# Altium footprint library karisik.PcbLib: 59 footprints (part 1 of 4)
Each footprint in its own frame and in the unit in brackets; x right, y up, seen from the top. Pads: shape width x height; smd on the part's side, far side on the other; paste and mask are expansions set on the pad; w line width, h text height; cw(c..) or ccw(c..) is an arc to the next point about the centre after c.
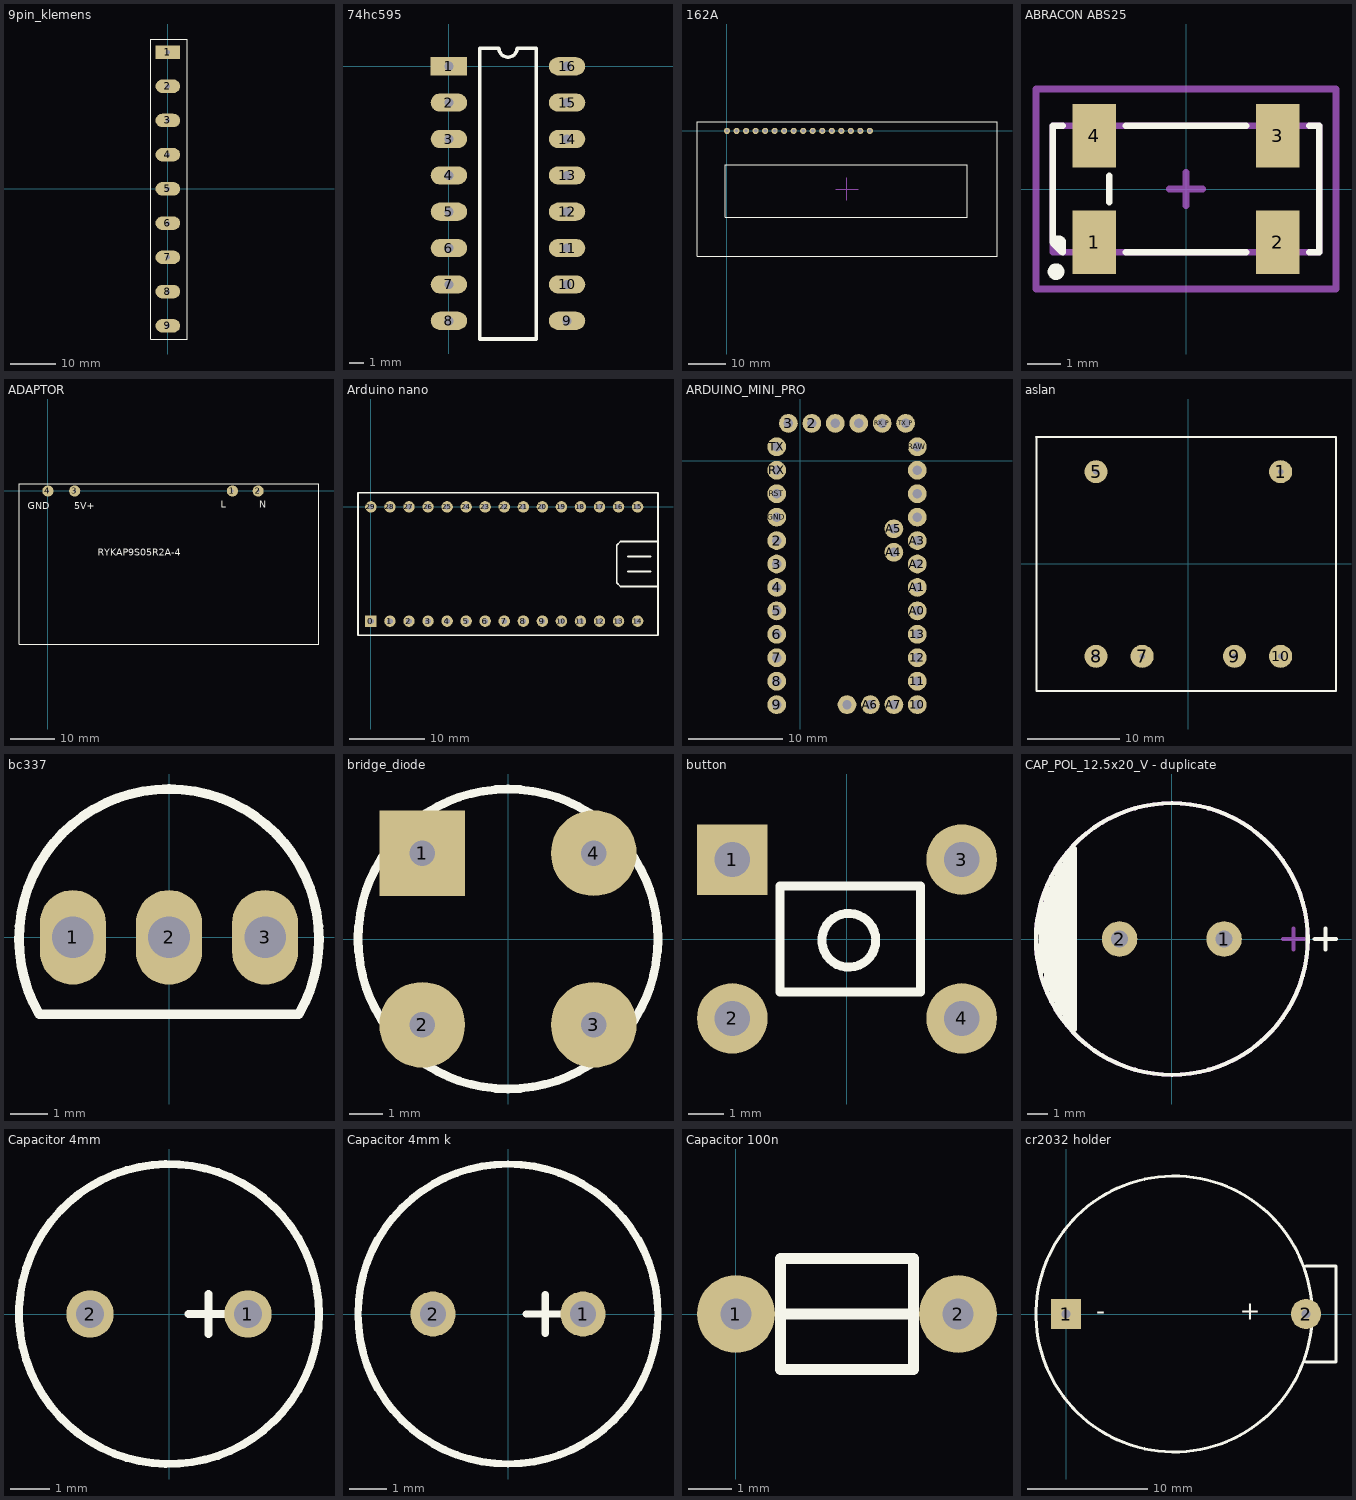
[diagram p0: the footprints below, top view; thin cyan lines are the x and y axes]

## 9pin_klemens [mm]
pads (9):
  rect 5.5x3 hole 1: 1(0,30.48)
  oval 5.5x3 hole 1: 2(0,22.86) 3(0,15.24) 4(0,7.62) 5(0,0) 6(0,-7.62) 7(0,-15.24) 8(0,-22.86) 9(0,-30.48)
Top Overlay:
  lines w0.254: -3.8,-33.42 4.3,-33.42 4.3,33.38 -3.8,33.38 -3.8,-33.42

## 74hc595 [mil]
pads (16):
  rect 100x50 hole 25: 1(0,0)
  oval 100x50 hole 25: 2(0,-100) 3(0,-200) 4(0,-300) 5(0,-400) 6(0,-500) 7(0,-600) 8(0,-700) 9(325,-700) 10(325,-600) 11(325,-500) 12(325,-400) 13(325,-300) 14(325,-200) 15(325,-100) 16(325,0)
Top Overlay:
  lines w10: 85,-750 240,-750 240,50 187.5,50 cw(c162.5,50) 137.5,50 85,50 85,-750

## 162A [mil]
pads (16):
  round 65 hole 35.43: 1(0,0) 2(100,0) 3(200,0) 4(300,0) 5(400,0) 6(500,0) 7(600,0) 8(700,0) 9(800,0) 10(900,0) 11(1000,0) 12(1100,0) 13(1200,0) 14(1300,0) 15(1400,0) 16(1500,0)
Top Overlay:
  lines w7.87: -314.96,-1318.9 2834.65,-1318.9 2834.65,98.43 -314.96,98.43 -314.96,-1318.9 ; -19.68,-905.51 2519.69,-905.51 2519.69,-354.33 -19.68,-354.33 -19.68,-905.51
Mechanical 15:
  lines w10: 1141.73,-610.24 1377.95,-610.24 ; 1259.84,-728.35 1259.84,-492.13

## ABRACON ABS25 [mm]
height 2.5
pads (4):
  rect 1.3x1.9 smd: 1(-2.75,-1.6) 2(2.75,-1.6) 3(2.75,1.6) 4(-2.75,1.6)
Top Overlay:
  circle w0.25: c-3.9,-2.48 r0.125
  region: -4,-1.5 -4,-1.6 -3.7,-1.9 -3.7,-1.6 -3.8,-1.5
  lines w0.2: -3.7,1.9 -4,1.9 -4,0 -4,-1.6 ; -2.3,-0.4 -2.3,0.4 ; -1.8,-1.9 1.8,-1.9 ; -1.8,1.9 1.8,1.9 ; 3.7,-1.9 4,-1.9 4,0 4,1.9 3.7,1.9 ; -4,-1.6 cw(c-3.9,-1.6) -3.9,-1.5 -3.8,-1.5 cw(c-3.8,-1.6) -3.7,-1.6 -3.7,-1.9 -4,-1.6
Mechanical 1:
  lines w0.2: -4,-1.9 -4,1.9 4,1.9 4,-1.9 -4,-1.9
Mechanical 15:
  lines w0.2: -0.5,0 0.5,0 ; 0,-0.5 0,0.5 ; -4.5,-3 -4.5,3 4.5,3 4.5,-3 -4.5,-3
3D body: height 2.5, standoff 0, extent -4,-1.9 4,1.9

## ADAPTOR [mm]
pads (4):
  round 2.5 hole 0.6: 1(41.453,0) 2(47.244,0) 3(6.02,0) 4(0,0)
Top Overlay:
  lines w0.254: -1.993,1.609 -6.493,1.609 ; 0,1.6 -6.485,1.6 ; 41.453,1.6 -6.485,1.6 ; -6.493,1.609 60.909,1.609 60.909,-34.417 -6.493,-34.417 -6.493,1.609 ; -6.493,1.609 -6.485,1.6
  text "RYKAP9S05R2A-4" at 11.227,-14.554 h1.52
  text "GND" at -4.521,-4.089 h1.52
  text "5V+" at 5.944,-4.089 h1.52
  text "L" at 38.811,-3.785 h1.52
  text "N" at 47.498,-3.785 h1.52

## Arduino nano [mil] "arduino nano"
height 1700
pads (30):
  rect 60x60 hole 30: 0(0,-600)
  round 60 hole 30: 1(100,-600) 2(200,-600) 3(300,-600) 4(400,-600) 5(500,-600) 6(600,-600) 7(700,-600) 8(800,-600) 9(900,-600) 10(1000,-600) 11(1100,-600) 12(1200,-600) 13(1300,-600) 14(1400,-600) 15(1400,0) 16(1300,0) 17(1200,0) 18(1100,0) 19(1000,0) 20(900,0) 21(800,0) 22(700,0) 23(600,0) 24(500,0) 25(400,0) 26(300,0) 27(200,0) 28(100,0) 29(0,0)
Top Overlay:
  lines w10: 1349.61,-339.37 1467.72,-339.37 ; 1349.61,-260.63 1467.72,-260.63 ; 1507.09,-418.11 1329.92,-418.11 1310.24,-418.11 1290.55,-398.43 1290.55,-359.06 1290.55,-201.57 1310.24,-181.89 1507.09,-181.89 ; -67.72,-674.02 -67.72,14.96 -67.72,74.02 1507.09,74.02 1507.09,34.65 1507.09,-674.02 -67.72,-674.02

## ARDUINO_MINI_PRO [mm]
pads (35):
  round 2 hole 1: 2(-2.5,-8.5) 2(1.25,4) 3(-2.5,-11) 3(-1.25,4) 4(-2.5,-13.5) 5(-2.5,-16) 6(-2.5,-18.5) 7(-2.5,-21) 8(-2.5,-23.5) 9(-2.5,-26) 10(12.5,-26) 11(12.5,-23.5) 12(12.5,-21) 13(12.5,-18.5) A0(12.5,-16) A1(12.5,-13.5) A2(12.5,-11) A3(12.5,-8.5) A4(10,-9.75) A5(10,-7.25) A6(7.5,-26) A7(10,-26) GND(-2.5,-6) GND_2(12.5,-1) GND_P(3.75,4) GND_SPI(5,-26) RAW(12.5,1.5) RST(-2.5,-3.5) RST_2(12.5,-3.5) RST_P(6.25,4) RX(-2.5,-1) RX_P(8.75,4) TX(-2.5,1.5) TX_P(11.25,4) VCC_2(12.5,-6)

## aslan [mm]
pads (6):
  round 2.5 hole 0.6: 1(10,10) 5(-10,10) 7(-5,-10) 8(-10,-10) 9(5,-10) 10(10,-10)
Top Overlay:
  lines w0.254: -16.5,13.75 16,13.75 16,-13.75 -16.4,-13.75 -16.45,-13.7 -16.45,13.75 -11.95,13.75

## bc337 [mm]
height 10
pads (3):
  oval 1.75x2.5 hole 1.1: 1(-2.54,0) 2(0,0) 3(2.54,0)
Top Overlay:
  lines w0.254: -3.429,-2.032 cw(c0,-0.043) 3.429,-2.032 -3.429,-2.032
Mechanical 15:
  lines w0.2: -0.5,0 0.5,0 ; 0,-0.5 0,0.5

## bridge_diode [mil]
height 217
pads (4):
  rect 100x100 hole 30: 1(-100,100)
  round 100 hole 30: 2(-100,-100) 3(100,-100) 4(100,100)
Top Overlay:
  circle w10: c0,0 r174.83

## button [mm]
pads (4):
  rect 2x2 hole 1: 1(-3.25,2.25)
  round 2 hole 1: 2(-3.25,-2.25) 3(3.25,2.25) 4(3.25,-2.25)
Top Overlay:
  circle w0.254: c0.052,-0.036 r0.762
  lines w0.254: -1.9,-1.5 2.076,-1.5 2.076,-1.179 2.076,1.107 2.076,1.5 -1.9,1.5 -1.9,-1.5

## CAP_POL_12.5x20_V - duplicate [mm]
pads (2):
  round 1.7 hole 0.8: 1(2.5,0) 2(-2.5,0)
Top Overlay:
  circle w0.2: c0,0 r6.5
  lines w0.2: 6.838,0 7.854,0 ; 7.346,-0.508 7.346,0.508
  lines w0.3: -6.223,-1.524 -6.223,1.651 ; -5.969,-2.413 -5.969,2.413 ; -5.715,-2.921 -5.715,2.921 ; -5.461,-3.302 -5.461,3.175 ; -5.334,-3.556 -5.334,3.556 ; -5.08,-3.81 -5.08,3.81 ; -4.953,-2.286 -4.953,4.064 ; -4.699,-4.318 -4.699,4.318 ; -4.953,4.064 -4.953,-4.064 -4.953,4.064
Mechanical 13:
  circle w0.2: c0,0 r6.5
  lines w0.2: 5.314,0 6.33,0 ; 5.822,-0.508 5.822,0.508
  text ".Designator" at -2.159,-3.175 h2.5
3D body: height 20.01, standoff -2.7, extent -6.206,-6.25 6.25,6.25

## Capacitor 4mm [mm]
pads (2):
  round 1.2 hole 0.7: 1(2,0) 2(-2,0)
Top Overlay:
  circle w0.2: c0,0 r3.8
  lines w0.2: 0.492,0 1.508,0 ; 1,-0.508 1,0.508

## Capacitor 4mm k [mm]
pads (2):
  round 1.2 hole 0.7: 1(2,0) 2(-2,0)
Top Overlay:
  circle w0.2: c0,0 r4
  lines w0.2: 0.492,0 1.508,0 ; 1,-0.508 1,0.508

## Capacitor 100n [mil]
pads (2):
  round 70 hole 28: 1(0,0) 2(200,0)
Top Overlay:
  lines w10: 40,0 130,0 ; 70,0 160,0 ; 160,0 160,-50 40,-50 40,50 160,50 160,0

## cr2032 holder [mil]
pads (2):
  rect 100x100 hole 30: 1(0,0)
  round 100 hole 30: 2(787.4,0)
Top Overlay:
  circle w10: c354.33,0 r452.76
  lines w10: 787.4,-157.48 885.83,-157.48 885.83,0 885.83,157.48 787.4,157.48
  text "-" at 98.43,-19.68 h60
  text "+" at 570.87,-19.68 h60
